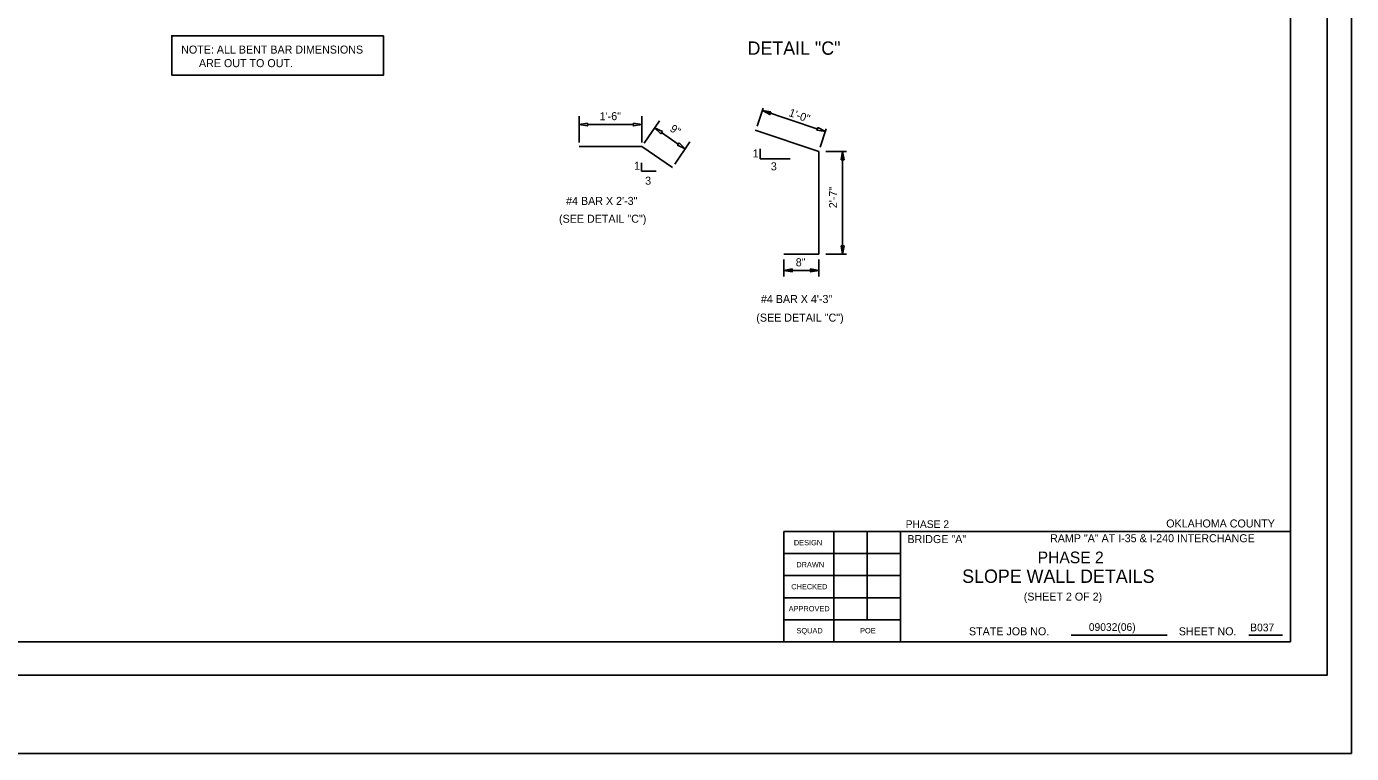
# Model space of a CAD drawing. Extents: x 570 to 2152770, y 726 to 139926.
# Drawn here: x 2151654.86 to 2151674.73, y 139318.2 to 139329.09 of the extents above; entities that cross this region are included whole.
import ezdxf

# ---------------------------------------------------------------- set-up
doc = ezdxf.new("R2010")
doc.units = 0
for name, color, linetype in [('4', 7, 'Continuous'), ('PR_Dimensions', 7, 'Continuous'), ('SHT_Plot_Shape_Full', 7, 'Continuous'), ('SHT_Plot_Shape_Half', 7, 'Continuous'), ('SHT_Sheet_Border', 7, 'Continuous'), ('SHT_Standard_Sheet_Lines', 7, 'Continuous'), ('SHT_Standard_Sheet_Txt', 7, 'Continuous'), ('T', 7, 'Continuous'), ('T-Title', 7, 'Continuous')]:
    doc.layers.add(name, color=color, linetype=linetype)

msp = doc.modelspace()

# ---------------------------------------------------------------- linework, layer by layer
at = {"layer": '4'}
for p, q in [((2151665.786, 139327.537), (2151666.739, 139327.22)), ((2151666.739, 139327.22), (2151666.739, 139325.678)), ((2151666.739, 139325.678), (2151666.217, 139325.678))]:
    msp.add_line(p, q, dxfattribs=at)
msp.add_lwpolyline([(2151663.146, 139327.292), (2151664.088, 139327.292), (2151664.547, 139326.979)], dxfattribs=at)
at = {"layer": 'PR_Dimensions'}
for p, q in [((2151665.816, 139327.599), (2151665.907, 139327.87)), ((2151663.146, 139327.354), (2151663.146, 139327.748)), ((2151664.088, 139327.354), (2151664.088, 139327.748)), ((2151664.123, 139327.344), (2151664.35, 139327.676)), ((2151665.894, 139327.833), (2151666.728, 139327.554)), ((2151663.272, 139327.623), (2151663.962, 139327.623)), ((2151664.383, 139327.501), (2151664.634, 139327.33)), ((2151666.761, 139327.284), (2151666.853, 139327.559)), ((2151664.582, 139327.031), (2151664.809, 139327.363)), ((2151665.86, 139327.259), (2151665.86, 139327.11)), ((2151664.082, 139327.05), (2151664.082, 139326.925)), ((2151665.86, 139327.11), (2151666.309, 139327.11)), ((2151666.846, 139327.22), (2151667.156, 139327.22)), ((2151667.098, 139327.22), (2151667.098, 139325.72)), ((2151664.082, 139326.925), (2151664.302, 139326.925)), ((2151666.846, 139325.678), (2151667.156, 139325.678)), ((2151666.217, 139325.599), (2151666.217, 139325.345)), ((2151666.739, 139325.599), (2151666.739, 139325.345)), ((2151666.217, 139325.437), (2151666.739, 139325.437))]:
    msp.add_line(p, q, dxfattribs=at)
for points in [[(2151660.215, 139328.953), (2151657.039, 139328.953), (2151657.039, 139328.364), (2151660.215, 139328.364)], [(2151663.272, 139327.644), (2151663.272, 139327.602), (2151663.146, 139327.623)], [(2151663.962, 139327.644), (2151663.962, 139327.602), (2151664.088, 139327.623)], [(2151666.02, 139327.813), (2151666.007, 139327.773), (2151665.894, 139327.833)], [(2151664.395, 139327.519), (2151664.371, 139327.484), (2151664.279, 139327.572)], [(2151666.727, 139327.578), (2151666.713, 139327.539), (2151666.839, 139327.519)], [(2151664.646, 139327.347), (2151664.623, 139327.313), (2151664.738, 139327.259)], [(2151667.077, 139327.094), (2151667.119, 139327.094), (2151667.098, 139327.22)], [(2151667.077, 139325.804), (2151667.119, 139325.804), (2151667.098, 139325.678)], [(2151666.343, 139325.458), (2151666.343, 139325.416), (2151666.217, 139325.437)], [(2151666.614, 139325.458), (2151666.614, 139325.416), (2151666.739, 139325.437)]]:
    msp.add_lwpolyline(points, close=True, dxfattribs=at)
at = {"layer": 'SHT_Plot_Shape_Full'}
msp.add_lwpolyline([(2151638.727, 139342.197), (2151674.727, 139342.197), (2151674.727, 139318.197), (2151638.727, 139318.197)], close=True, dxfattribs=at)
at = {"layer": 'SHT_Plot_Shape_Half'}
msp.add_lwpolyline([(2151640.365, 139341.372), (2151674.365, 139341.372), (2151674.365, 139319.372), (2151640.365, 139319.372)], close=True, dxfattribs=at)
at = {"layer": 'SHT_Sheet_Border'}
for p, q in [((2151666.215, 139319.872), (2151666.215, 139321.522)), ((2151666.215, 139321.522), (2151673.815, 139321.522)), ((2151667.965, 139319.872), (2151667.965, 139321.523))]:
    msp.add_line(p, q, dxfattribs=at)
msp.add_lwpolyline([(2151673.815, 139319.872), (2151642.315, 139319.872), (2151642.315, 139340.872), (2151673.815, 139340.872)], close=True, dxfattribs=at)
at = {"layer": 'SHT_Standard_Sheet_Lines'}
for p, q in [((2151666.965, 139319.872), (2151666.965, 139321.523)), ((2151667.465, 139320.202), (2151667.465, 139321.523)), ((2151670.526, 139319.968), (2151671.966, 139319.968)), ((2151673.19, 139319.968), (2151673.693, 139319.968))]:
    msp.add_line(p, q, dxfattribs=at)
for points in [[(2151667.965, 139321.192), (2151666.215, 139321.192)], [(2151667.965, 139320.862), (2151666.215, 139320.862)], [(2151667.965, 139320.532), (2151666.215, 139320.532)], [(2151667.965, 139320.202), (2151666.215, 139320.202)]]:
    msp.add_lwpolyline(points, dxfattribs=at)

# ---------------------------------------------------------------- texts
at = {"layer": 'Defpoints'}
msp.add_text('PHASE 2', height=0.175, dxfattribs=at).set_placement((2151670.023, 139321.048))
at = {"layer": 'SHT_Standard_Sheet_Txt'}
for s, height, p in [('DESIGN', 0.08, (2151666.367, 139321.317)), ('DRAWN', 0.08, (2151666.403, 139320.987)), ('CHECKED', 0.08, (2151666.328, 139320.657)), ('APPROVED', 0.08, (2151666.289, 139320.327)), ('SQUAD', 0.08, (2151666.406, 139319.997)), ('POE', 0.08, (2151667.36, 139319.997)), ('STATE JOB NO.', 0.12, (2151668.992, 139319.968)), ('SHEET NO. ', 0.12, (2151672.138, 139319.968))]:
    msp.add_text(s, height=height, dxfattribs=at).set_placement(p)
at = {"layer": 'T'}
for s, height, p in [('NOTE: ALL BENT BAR DIMENSIONS        ', 0.12, (2151657.18, 139328.686)), ('      ARE OUT TO OUT.', 0.12, (2151657.18, 139328.483)), ('1\'-6"', 0.12, (2151663.455, 139327.688)), ('1', 0.12, (2151665.749, 139327.13)), ('1', 0.12, (2151663.971, 139326.945)), ('3', 0.12, (2151666.021, 139326.936)), ('3', 0.12, (2151664.137, 139326.721)), ('#4 BAR X 2\'-3"', 0.12, (2151662.952, 139326.418)), ('(SEE DETAIL "C")', 0.12, (2151662.846, 139326.151)), ('8"', 0.12, (2151666.395, 139325.499)), ('#4 BAR X 4\'-3"', 0.12, (2151665.873, 139324.948)), ('(SEE DETAIL "C")', 0.12, (2151665.804, 139324.669)), ('PHASE 2', 0.1152, (2151668.043, 139321.576)), ('OKLAHOMA COUNTY', 0.11979, (2151671.95, 139321.584)), ('RAMP "A" AT I-35 & I-240 INTERCHANGE', 0.11979, (2151670.208, 139321.363)), ('BRIDGE "A" ', 0.12, (2151668.069, 139321.35)), ('(SHEET 2 OF 2)', 0.11979, (2151669.814, 139320.488)), ('09032(06)', 0.1152, (2151670.789, 139320.034)), ('B037', 0.1152, (2151673.209, 139320.028))]:
    msp.add_text(s, height=height, dxfattribs=at).set_placement(p)
for s, rotation, p in [('1\'-0"', 340.8033, (2151666.281, 139327.753)), ('9"', 325.7113, (2151664.497, 139327.534)), ('2\'-7"', 90, (2151667.015, 139326.369))]:
    msp.add_text(s, height=0.12, rotation=rotation, dxfattribs=at).set_placement(p)
at = {"layer": 'T-Title'}
for s, p in [('DETAIL "C"', (2151665.672, 139328.668)), ('SLOPE WALL DETAILS', (2151668.89, 139320.754))]:
    msp.add_text(s, height=0.2, dxfattribs=at).set_placement(p)

doc.saveas('drawing.dxf')
